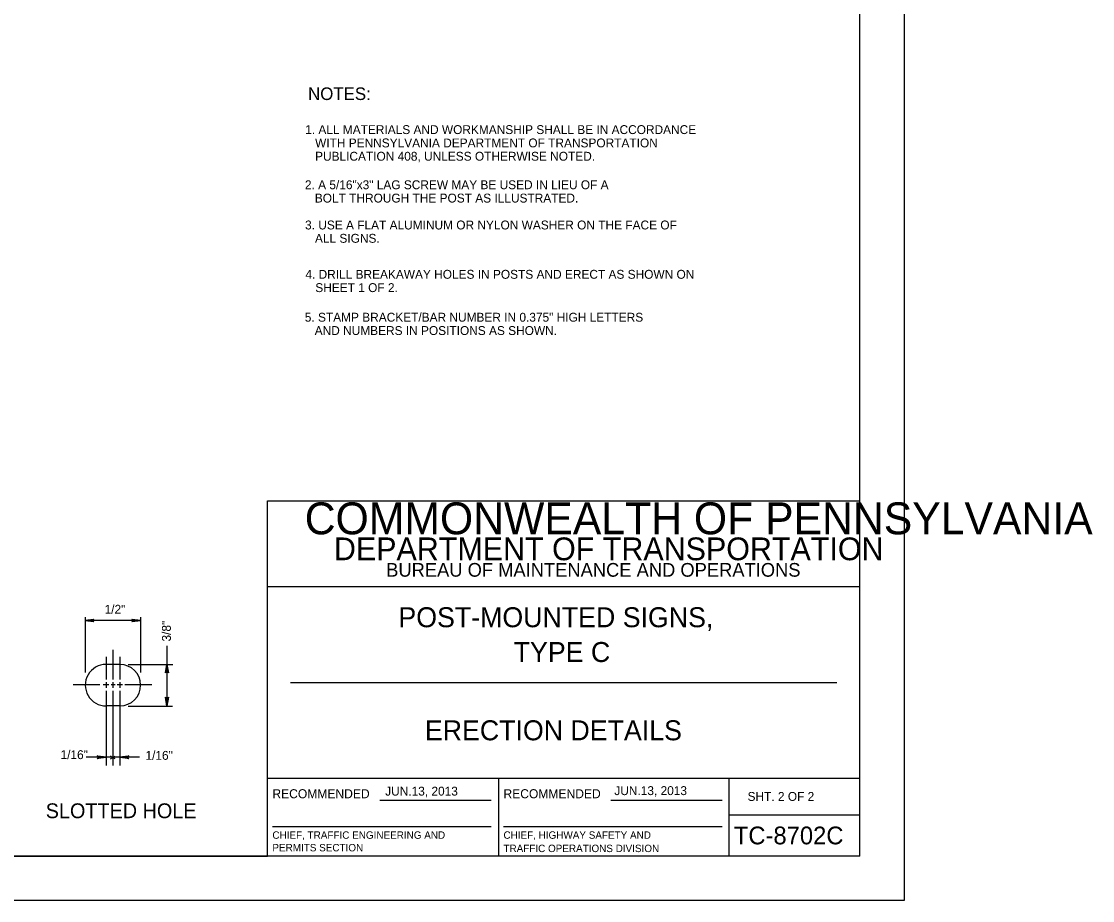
# Model space of a CAD drawing. Extents: x 648590 to 650336, y 294467 to 295061.
# Drawn here: x 649974.1 to 650335.6, y 294467.4 to 294764.4 of the extents above; entities that cross this region are included whole.
import ezdxf

# ---------------------------------------------------------------- set-up
doc = ezdxf.new("R2010")
doc.units = 0
for name, color, linetype in [('1', 7, 'Continuous'), ('2', 7, 'Continuous'), ('3', 7, 'Continuous'), ('PLT-BNDY', 7, 'Continuous')]:
    doc.layers.add(name, color=color, linetype=linetype)

msp = doc.modelspace()

# ---------------------------------------------------------------- linework, layer by layer
at = {"layer": '1'}
for p, q in [((650257.1, 294482.45), (650257.1, 295046.45)), ((650057.1, 294482.45), (650057.1, 294602.45)), ((650057.1, 294602.45), (650257.1, 294602.45)), ((650257.1, 294573.45), (650057.1, 294573.45)), ((650064.85, 294541.13), (650249.35, 294541.13)), ((650057.1, 294508.82), (650257.1, 294508.82)), ((650135.1, 294508.82), (650135.1, 294482.45)), ((650212.97, 294482.45), (650212.97, 294508.82)), ((650095.03, 294501.39), (650132.65, 294501.39)), ((650173.03, 294501.39), (650210.65, 294501.39)), ((650212.97, 294496.45), (650257.1, 294496.45)), ((650058.78, 294492.5), (650132.65, 294492.5)), ((650136.78, 294492.5), (650210.65, 294492.5)), ((650257.1, 294482.45), (649471.1, 294482.45)), ((649471.1, 294482.45), (650057.1, 294482.45))]:
    msp.add_line(p, q, dxfattribs=at)
at = {"layer": '2'}
for p, q in [((650007.31, 294547.24), (650002.63, 294547.24)), ((650007.31, 294533.23), (650002.68, 294533.23))]:
    msp.add_line(p, q, dxfattribs=at)
for centre, start, end in [((650002.63, 294540.23), 90, 270.4112), ((650007.3, 294540.23), 270, 90)]:
    msp.add_arc(centre, 7.01, start, end, dxfattribs=at)
at = {"layer": '3'}
for p, q in [((649995.56, 294563.24), (649995.56, 294544.55)), ((650014.31, 294563.24), (650014.31, 294544.55)), ((650014.31, 294562.12), (649995.56, 294562.12)), ((650004.93, 294552.18), (650004.93, 294542.18)), ((650023.18, 294553.46), (650023.18, 294533.17)), ((650002.68, 294549.8), (650002.68, 294542.18)), ((650007.31, 294549.8), (650007.31, 294542.18)), ((650010.06, 294547.21), (650025.18, 294547.21)), ((650002.68, 294541.18), (650002.68, 294539.3)), ((650004.93, 294541.18), (650004.93, 294539.3)), ((650007.31, 294541.18), (650007.31, 294539.3)), ((650000.56, 294540.3), (649991.56, 294540.3)), ((650003.56, 294540.3), (650001.68, 294540.3)), ((650002.68, 294538.3), (650002.68, 294513.09)), ((650005.68, 294540.3), (650004.31, 294540.3)), ((650004.93, 294538.3), (650004.93, 294513.09)), ((650008.18, 294540.3), (650006.43, 294540.3)), ((650007.31, 294538.3), (650007.31, 294513.09)), ((650018.06, 294540.3), (650008.93, 294540.3)), ((650010.06, 294533.17), (650025.06, 294533.17)), ((650002.68, 294515.89), (649995.87, 294515.89)), ((650007.31, 294515.89), (650002.68, 294515.89)), ((650004.18, 294515.39), (650005.68, 294516.27)), ((650005.68, 294515.39), (650004.18, 294516.27)), ((650013.87, 294515.89), (650007.31, 294515.89))]:
    msp.add_line(p, q, dxfattribs=at)
for points in [[(649998.43, 294561.74), (649998.31, 294561.87), (649995.56, 294562.12), (649998.43, 294561.74), (649998.56, 294561.62), (649995.56, 294562.12), (649998.31, 294562.24), (649998.43, 294562.37), (649995.56, 294562.12), (649998.56, 294562.49), (649998.43, 294562.37)], [(650011.43, 294562.37), (650011.56, 294562.24), (650014.31, 294562.12), (650011.43, 294562.37), (650011.31, 294562.49), (650014.31, 294562.12), (650011.56, 294561.99), (650011.43, 294561.74), (650014.31, 294562.12), (650011.31, 294561.62), (650011.43, 294561.74)], [(650022.81, 294544.46), (650023.06, 294544.59), (650023.18, 294547.21), (650022.81, 294544.46), (650022.68, 294544.34), (650023.18, 294547.21), (650023.43, 294544.59), (650023.56, 294544.46), (650023.18, 294547.21), (650023.68, 294544.34), (650023.56, 294544.46)], [(650023.56, 294536.04), (650023.43, 294535.92), (650023.18, 294533.17), (650023.56, 294536.04), (650023.68, 294536.17), (650023.18, 294533.17), (650023.06, 294535.92), (650022.93, 294536.04), (650023.18, 294533.17), (650022.68, 294536.17), (650022.93, 294536.04)], [(649999.81, 294516.27), (649999.93, 294516.02), (650002.68, 294515.89), (649999.81, 294516.27), (649999.68, 294516.39), (650002.68, 294515.89), (649999.93, 294515.77), (649999.81, 294515.52), (650002.68, 294515.89), (649999.68, 294515.39), (649999.81, 294515.52)], [(650010.06, 294515.52), (650010.06, 294515.77), (650007.31, 294515.89), (650010.06, 294515.52), (650010.31, 294515.39), (650007.31, 294515.89), (650010.06, 294516.02), (650010.06, 294516.27), (650007.31, 294515.89), (650010.31, 294516.39), (650010.06, 294516.27)]]:
    msp.add_lwpolyline(points, dxfattribs=at)
at = {"layer": 'PLT-BNDY'}
msp.add_lwpolyline([(649431.1, 295061.45), (650272.1, 295061.45), (650272.1, 294467.45), (649431.1, 294467.45)], close=True, dxfattribs=at)

# ---------------------------------------------------------------- texts
at = {"layer": '1'}
for s, height, p in [('COMMONWEALTH OF PENNSYLVANIA', 10.7828, (650069.69, 294591.18)), ('DEPARTMENT OF TRANSPORTATION', 7.6837, (650079.55, 294582.43)), ('BUREAU OF MAINTENANCE AND OPERATIONS', 4.6253, (650097.19, 294576.86)), ('POST-MOUNTED SIGNS,', 6.75, (650101.32, 294559.79)), ('TYPE C', 6.75, (650140.23, 294548.04)), ('ERECTION DETAILS', 6.75, (650110.25, 294521.6)), ('RECOMMENDED', 3.048, (650058.78, 294502.02)), ('RECOMMENDED', 3.048, (650136.78, 294502.02)), ('SHT. 2 OF 2', 3, (650219.18, 294501.13)), ('CHIEF, TRAFFIC ENGINEERING AND', 2.5, (650058.78, 294488.33)), ('CHIEF, HIGHWAY SAFETY AND', 2.5, (650136.78, 294488.33)), ('TC-8702C', 6, (650214.55, 294486.45)), ('PERMITS SECTION', 2.5, (650058.78, 294484.08)), ('TRAFFIC OPERATIONS DIVISION', 2.5, (650136.78, 294483.83))]:
    msp.add_text(s, height=height, dxfattribs=at).set_placement(p)
at = {"layer": '2'}
for s, height, p in [('JUN.13, 2013', 3, (650096.86, 294502.92)), ('JUN.13, 2013', 3, (650174.21, 294503.09)), ('SLOTTED HOLE', 5, (649982.27, 294495.29))]:
    msp.add_text(s, height=height, dxfattribs=at).set_placement(p)
at = {"layer": '3'}
for s, height, p in [('NOTES:', 4.25, (650070.83, 294737.89)), ('1. ALL MATERIALS AND WORKMANSHIP SHALL BE IN ACCORDANCE', 3, (650069.85, 294726.39)), ('   WITH PENNSYLVANIA DEPARTMENT OF TRANSPORTATION', 3, (650069.85, 294721.89)), ('   PUBLICATION 408, UNLESS OTHERWISE NOTED.', 3, (650069.85, 294717.39)), ('2. A 5/16"x3" LAG SCREW MAY BE USED IN LIEU OF A', 3, (650069.76, 294707.76)), ('   BOLT THROUGH THE POST AS ILLUSTRATED.', 3, (650069.76, 294703.26)), ('3. USE A FLAT ALUMINUM OR NYLON WASHER ON THE FACE OF', 3, (650069.81, 294694.17)), ('   ALL SIGNS.', 3, (650069.81, 294689.67)), ('4. DRILL BREAKAWAY HOLES IN POSTS AND ERECT AS SHOWN ON', 3, (650069.92, 294677.51)), ('   SHEET 1 OF 2.', 3, (650069.92, 294673.01)), ('5. STAMP BRACKET/BAR NUMBER IN 0.375" HIGH LETTERS ', 3, (650069.72, 294663.01)), ('   AND NUMBERS IN POSITIONS AS SHOWN.', 3, (650069.72, 294658.51)), ('1/2"', 3, (650002.14, 294564.35)), ('1/16"', 3, (649987.27, 294515.24)), ('1/16"', 3, (650015.94, 294515))]:
    msp.add_text(s, height=height, dxfattribs=at).set_placement(p)
msp.add_text('3/8"', height=3, rotation=90, dxfattribs=at).set_placement((650024.51, 294554.97))

doc.saveas('drawing.dxf')
